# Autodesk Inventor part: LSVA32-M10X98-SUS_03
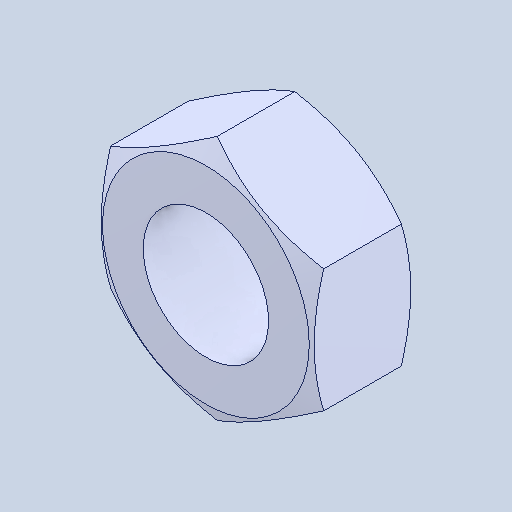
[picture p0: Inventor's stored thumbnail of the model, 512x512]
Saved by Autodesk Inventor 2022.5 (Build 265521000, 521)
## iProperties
Created: 2024-08
Part Number: LSVA32-M10X98-SUS_03
Material: 一般
Document SubType Name: Modeling
Designer: ImaoCorp
Density: 1 g/cm^3
Appearance: 既定
Author: ImaoCorp
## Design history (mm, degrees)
feature "LSVA32-M10X98-SUS_03"
node "ソリッド1"
